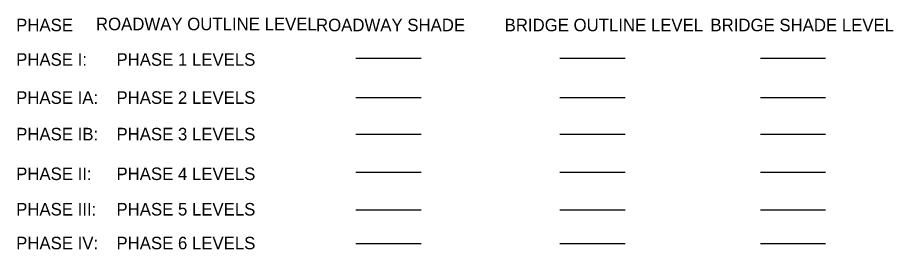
# Model space of a CAD drawing. Extents: x 2133551 to 2156187, y 140366 to 148242.
# Drawn here: x 2133551 to 2140536, y 145856 to 147707 of the extents above; entities that cross this region are included whole.
import ezdxf

# ---------------------------------------------------------------- set-up
doc = ezdxf.new("R2010")
doc.units = 0
for name, color, linetype in [('Default', 7, 'Continuous'), ('EX_Align', 7, 'Continuous'), ('INR_InRoads_Unassigned', 7, 'Continuous'), ('MTL_Concrete', 7, 'Continuous'), ('Ph1-PR-Dividing Strip', 7, 'Continuous'), ('Ph1-PR-Slopewall', 7, 'Continuous'), ('PH1a-PR-I240-Shld', 7, 'Continuous'), ('PH2-PR-Barrier', 7, 'Continuous'), ('PR-ML-Curb', 7, 'Continuous'), ('PR-Ramp-Curb', 7, 'Continuous'), ('PR_Align_Ramp_A', 7, 'Continuous'), ('PR_Align_Ramp_E', 7, 'Continuous'), ('PR_Align_Ramp_F', 7, 'Continuous'), ('PR_Align_Retaining_Wall_C', 7, 'Continuous'), ('PR_Curb_Back', 7, 'Continuous'), ('PR_Curb_Face', 7, 'Continuous'), ('PR_Drive_Com', 7, 'Continuous'), ('PR_DTM_Exterior', 7, 'Continuous'), ('PR_Phasing_Pavement_6', 7, 'Continuous'), ('PR_Sidewalk', 7, 'Continuous'), ('PR_Txt', 7, 'Continuous'), ('PROP-I-35-SHLDR', 7, 'Continuous'), ('PROP-RAMP', 7, 'Continuous'), ('PROP-RAMP-SHLDR', 7, 'Continuous')]:
    doc.layers.add(name, color=color, linetype=linetype)

msp = doc.modelspace()

# ---------------------------------------------------------------- linework, layer by layer
msp.add_line((2139995.4, 146471.3), (2139474.7, 146471.3))
at = {"layer": 'INR_InRoads_Unassigned'}
msp.add_line((2136770.4, 146773.2), (2136249.8, 146773.2), dxfattribs=at)
at = {"layer": 'MTL_Concrete'}
msp.add_line((2138397.4, 145900.7), (2137876.7, 145900.7), dxfattribs=at)
at = {"layer": 'Ph1-PR-Dividing Strip'}
msp.add_line((2138397.4, 147066.7), (2137876.7, 147066.7), dxfattribs=at)
at = {"layer": 'Ph1-PR-Slopewall'}
msp.add_line((2136770.4, 146169.5), (2136249.8, 146169.5), dxfattribs=at)
at = {"layer": 'PH1a-PR-I240-Shld'}
msp.add_line((2139995.4, 147066.7), (2139474.7, 147066.7), dxfattribs=at)
at = {"layer": 'PH2-PR-Barrier'}
msp.add_line((2136770.4, 146471.3), (2136249.8, 146471.3), dxfattribs=at)
at = {"layer": 'PR-ML-Curb'}
msp.add_line((2139995.4, 147381), (2139474.7, 147381), dxfattribs=at)
at = {"layer": 'PR-Ramp-Curb'}
msp.add_line((2138397.4, 147381), (2137876.7, 147381), dxfattribs=at)
at = {"layer": 'PR_Align_Ramp_E'}
msp.add_line((2139995.4, 146169.5), (2139474.7, 146169.5), dxfattribs=at)
at = {"layer": 'PR_Align_Retaining_Wall_C'}
msp.add_line((2136770.4, 147381), (2136249.8, 147381), dxfattribs=at)
at = {"layer": 'PR_Drive_Com'}
msp.add_line((2138397.4, 146169.5), (2137876.7, 146169.5), dxfattribs=at)
at = {"layer": 'PR_DTM_Exterior'}
msp.add_line((2138397.4, 146471.3), (2137876.7, 146471.3), dxfattribs=at)
at = {"layer": 'PR_Sidewalk'}
msp.add_line((2136770.4, 145900.7), (2136249.8, 145900.7), dxfattribs=at)
at = {"layer": 'PR_Txt'}
msp.add_line((2136770.4, 147066.7), (2136249.8, 147066.7), dxfattribs=at)
at = {"layer": 'PROP-I-35-SHLDR'}
msp.add_line((2139995.4, 145900.7), (2139474.7, 145900.7), dxfattribs=at)
at = {"layer": 'PROP-RAMP'}
msp.add_line((2139995.4, 146773.2), (2139474.7, 146773.2), dxfattribs=at)
at = {"layer": 'PROP-RAMP-SHLDR'}
msp.add_line((2138397.4, 146773.2), (2137876.7, 146773.2), dxfattribs=at)

# ---------------------------------------------------------------- texts
at = {"layer": 'Default'}
for s, p in [('PHASE', (2133540, 147596.9)), ('ROADWAY OUTLINE LEVEL', (2134176.3, 147605.1)), ('ROADWAY SHADE', (2135931.4, 147596.9)), ('BRIDGE OUTLINE LEVEL', (2137435.4, 147596.9)), ('BRIDGE SHADE LEVEL', (2139076.8, 147596.9))]:
    msp.add_text(s, height=100, dxfattribs=at).set_placement(p)
at = {"layer": 'EX_Align'}
for s, p in [('PHASE IA:', (2133540, 147018)), ('PHASE 2 LEVELS', (2134340, 147018))]:
    msp.add_text(s, height=100, dxfattribs=at).set_placement(p)
at = {"layer": 'PR_Align_Ramp_A'}
for s, p in [('PHASE IB:', (2133540, 146726.7)), ('PHASE 3 LEVELS', (2134340, 146726.7))]:
    msp.add_text(s, height=100, dxfattribs=at).set_placement(p)
at = {"layer": 'PR_Align_Ramp_F'}
for s, p in [('PHASE II:', (2133540, 146410.1)), ('PHASE 4 LEVELS', (2134340, 146410.1))]:
    msp.add_text(s, height=100, dxfattribs=at).set_placement(p)
at = {"layer": 'PR_Curb_Back'}
for s, p in [('PHASE III:', (2133540, 146127.3)), ('PHASE 5 LEVELS', (2134340, 146127.3))]:
    msp.add_text(s, height=100, dxfattribs=at).set_placement(p)
at = {"layer": 'PR_Curb_Face'}
for s, p in [('PHASE IV:', (2133540, 145857.7)), ('PHASE 6 LEVELS', (2134340, 145857.7))]:
    msp.add_text(s, height=100, dxfattribs=at).set_placement(p)
at = {"layer": 'PR_Phasing_Pavement_6'}
for s, p in [('PHASE I:', (2133540, 147321.9)), ('PHASE 1 LEVELS', (2134340, 147321.9))]:
    msp.add_text(s, height=100, dxfattribs=at).set_placement(p)

doc.saveas('drawing.dxf')
